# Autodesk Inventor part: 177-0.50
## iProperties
Created: 2007-07
Part Number: 177-0.50
Document SubType Name: Modeling
Designer: btaylor
Density: 1 g/cm^3
Author: btaylor
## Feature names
1. Extrusion1
2. Mirror1
3. Extrusion2
4. Extrusion3
5. Fillet1
6. Fillet2
7. Chamfer1
8. Chamfer2
